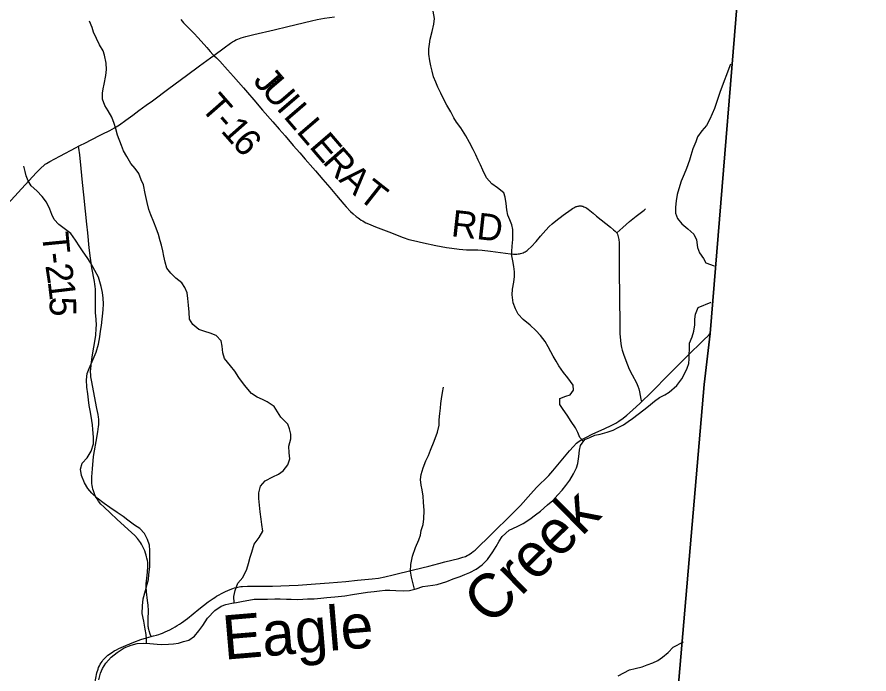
# Model space of a CAD drawing. Extents: x 1451455 to 1749751, y 218250 to 574981.
# Drawn here: x 1624093 to 1633736, y 328950 to 336380 of the extents above; entities that cross this region are included whole.
import ezdxf

# ---------------------------------------------------------------- set-up
doc = ezdxf.new("R2010")
doc.units = 0
for name, color, linetype in [('GM_X_Adjacent_County', 7, 'Continuous'), ('GM_X_County', 7, 'Continuous'), ('GM_X_County_Road', 7, 'Continuous'), ('GM_X_Minor_River', 7, 'Continuous'), ('GM_X_Minor_River_Text', 7, 'Continuous'), ('GM_X_Township', 7, 'Continuous'), ('GM_X_Township_Road', 7, 'Continuous'), ('GM_X_Township_Road_Text', 7, 'Continuous')]:
    doc.layers.add(name, color=color, linetype=linetype)

msp = doc.modelspace()

# ---------------------------------------------------------------- linework, layer by layer
at = {"layer": 'GM_X_Adjacent_County'}
msp.add_lwpolyline([(1628937.4, 298347.9), (1629433.5, 303775.2), (1629535.6, 304886.8), (1630089.4, 311112.5), (1630271.2, 313052.8), (1630419.2, 314553.1), (1630488.1, 315536.2), (1630722.1, 318179), (1630769.3, 318616.5), (1630954.3, 320912.7), (1631259.9, 324445.5), (1631493.2, 327825.1), (1631870, 332223.9), (1631938.7, 332800.9), (1632333.3, 337651.7), (1632719.3, 342502.4), (1633084.6, 347092.3), (1633092.9, 347196.5), (1633154.2, 348075.8), (1633223.5, 348841.9), (1633265.4, 349677.7), (1633735.7, 355307.8)], dxfattribs=at)
at = {"layer": 'GM_X_County'}
msp.add_lwpolyline([(1628937.4, 298347.9), (1629433.5, 303775.2), (1629535.6, 304886.8), (1630089.4, 311112.5), (1630271.2, 313052.8), (1630419.2, 314553.1), (1630488.1, 315536.2), (1630722.1, 318179), (1630769.3, 318616.5), (1630954.3, 320912.7), (1631259.9, 324445.5), (1631493.2, 327825.1), (1631870, 332223.9), (1631938.7, 332800.9), (1632333.3, 337651.7), (1632719.3, 342502.4), (1633084.6, 347092.3), (1633092.9, 347196.5), (1633154.2, 348075.8), (1633223.5, 348841.9), (1633265.4, 349677.7), (1633735.7, 355307.8)], dxfattribs=at)
at = {"layer": 'GM_X_County_Road'}
for points in [[(1631159.4, 332026.7), (1631263.8, 332125.8), (1631317.3, 332178.8), (1631434, 332298.6), (1631600.2, 332466.4), (1631643.9, 332510.9), (1631730.7, 332596), (1631811.6, 332672.8), (1631867.8, 332727.6), (1631918.3, 332779.8), (1631938.7, 332800.9)], [(1625610.6, 329374.1), (1625637.9, 329381.5), (1625671.2, 329390.2), (1625697.8, 329397.9), (1625717.1, 329404.2), (1625740.8, 329412.9), (1625770.6, 329425.3), (1625794.6, 329436.2), (1625824.4, 329450.5), (1625855.9, 329467), (1625881.9, 329481.2), (1625906.8, 329496.5), (1625932.6, 329513.1), (1625955.6, 329529.1), (1626021.1, 329578.1), (1626152.7, 329681.3), (1626258.3, 329764.8), (1626311.7, 329803.4), (1626330.8, 329815.8), (1626350.9, 329827.9), (1626380.9, 329844.6), (1626409.2, 329859.3), (1626446.2, 329877.3), (1626487.8, 329896.2), (1626535.1, 329916.1), (1626556.3, 329923.2), (1626573.1, 329927.9), (1626592.3, 329932.6), (1626608.9, 329935.4), (1626626.3, 329937.8), (1626645.1, 329939.7), (1626701.2, 329941.7), (1626986.5, 329944.3), (1627173.4, 329949.7), (1627274.7, 329955.5), (1627471, 329969.9), (1627628, 329982.3), (1627814.3, 329997.3), (1627945, 330009.3), (1628114.7, 330025.1), (1628186, 330034.9), (1628256.7, 330048), (1628349.1, 330069.6), (1628581.4, 330128.5), (1628753.4, 330170.4), (1628867.5, 330200), (1628934, 330217.9), (1629093.3, 330257), (1629139.4, 330269.6), (1629168.4, 330279.8), (1629189, 330288.6), (1629204.9, 330297), (1629221.8, 330307), (1629237.7, 330318), (1629257.1, 330333.6), (1629278.9, 330351.2), (1629326.9, 330397.5), (1629417.8, 330487.4), (1629527, 330596.4), (1629628.2, 330694.6), (1629733.8, 330797.6), (1629790.4, 330856.7), (1629908.4, 330988.8), (1629973.8, 331058.2), (1630111.2, 331194.4), (1630157.8, 331246.9), (1630345.5, 331472.7), (1630391.7, 331524.2), (1630427.1, 331558.9), (1630455.6, 331581.8), (1630486.2, 331601.7), (1630529.9, 331625.1), (1630609.6, 331664), (1630738.1, 331722.1), (1630824.1, 331762.4), (1630870, 331787.2), (1630905.9, 331809.7), (1630953.6, 331843.9), (1630994.1, 331876.8), (1631060.3, 331935.4), (1631144.9, 332012.9), (1631159.4, 332026.7)], [(1624973.5, 328843.6), (1624998.3, 328962.6), (1625010.2, 329004), (1625017.2, 329023.5), (1625025.3, 329040.9), (1625035.6, 329060.2), (1625044.8, 329075.8), (1625055.9, 329092.2), (1625066.2, 329105.5), (1625079.5, 329120.9), (1625092.9, 329135.1), (1625107, 329148), (1625122.7, 329161.5), (1625139.3, 329174.4), (1625154.8, 329185.1), (1625174, 329197.5), (1625194.2, 329209.5), (1625217.9, 329222.2), (1625246.7, 329237.3), (1625324.4, 329273), (1625415.5, 329310.8), (1625495.9, 329340.1), (1625558.6, 329360.1), (1625610.6, 329374.1)]]:
    msp.add_lwpolyline(points, dxfattribs=at)
at = {"layer": 'GM_X_Minor_River'}
for points in [[(1630504.1, 331580.4), (1630463.3, 331625.8), (1630442.1, 331680.1), (1630412.8, 331732.5), (1630365.9, 331807.2), (1630319, 331877.9), (1630273.9, 331942.5), (1630236.8, 331997.1), (1630235.7, 332065.2), (1630304.1, 332090.3), (1630354.3, 332107.6), (1630391, 332159.2), (1630387.8, 332215.3), (1630327.1, 332298.2), (1630278, 332358.9), (1630225.1, 332433.6), (1630195.9, 332486.1), (1630162.7, 332544.6), (1630133.5, 332595), (1630106.3, 332651.4), (1630069.2, 332710), (1630016.2, 332778.7), (1629965, 332833.4), (1629902, 332896.3), (1629820.9, 332957.4), (1629763.8, 333020.2), (1629734.7, 333080.7), (1629709.7, 333147.1), (1629697, 333239.3), (1629701.9, 333301.3), (1629715.1, 333381.2), (1629722, 333445.2), (1629722.8, 333499.2), (1629715.7, 333559.4), (1629704.6, 333623.6), (1629695.4, 333677.7), (1629694.1, 333729.8), (1629697, 333787.8), (1629704.1, 333865.8), (1629704.9, 333917.8), (1629703.7, 333975.9), (1629694.5, 334028.1), (1629669.3, 334086.5), (1629650.1, 334138.8), (1629637, 334199), (1629630, 334271.1), (1629619, 334341.3), (1629603.8, 334391.6), (1629530.6, 334448.6), (1629467.4, 334495.5), (1629408.3, 334560.3), (1629365.6, 334646.9), (1629338.5, 334709.3), (1629311.3, 334761.7), (1629286.2, 334822.1), (1629257.1, 334882.6), (1629214.2, 334961.2), (1629171.4, 335035.8), (1629116.7, 335126.6), (1629065.6, 335189.3), (1629036.4, 335239.8), (1629001.4, 335308.3), (1628958.5, 335384.9), (1628919.6, 335455.5), (1628888.5, 335519.9), (1628857.5, 335588.4), (1628832.3, 335642.8), (1628807.2, 335703.1), (1628790.2, 335767.4), (1628775, 335827.7), (1628765.9, 335885.8), (1628755, 335960), (1628753.9, 336020.1), (1628760.6, 336074.1), (1628769.4, 336130), (1628792.7, 336217.8), (1628809.9, 336299.6), (1628818.8, 336365.6), (1628802, 336447.8)], [(1626551.1, 329753.9), (1626545.3, 329827.1), (1626562.3, 329893), (1626591.5, 329976.7), (1626650.4, 330042), (1626693.7, 330133.5), (1626712.6, 330199.3), (1626731.7, 330271.1), (1626750.5, 330328.9), (1626775.8, 330418.7), (1626834.8, 330492), (1626875.8, 330563.5), (1626864.9, 330639.8), (1626857.8, 330699.9), (1626845, 330784.2), (1626836.1, 330860.3), (1626831.2, 330932.5), (1626830.1, 330998.6), (1626849.2, 331072.4), (1626902.1, 331133.8), (1626988.7, 331180.7), (1627051.1, 331209.9), (1627105.6, 331249.2), (1627156.6, 331316.6), (1627179.5, 331382.4), (1627172.5, 331452.5), (1627169.6, 331526.7), (1627192.8, 331608.4), (1627193.5, 331662.5), (1627178.4, 331720.7), (1627159.2, 331775), (1627080.4, 331854.1), (1627041.3, 331914.7), (1627004.1, 331973.2), (1626925, 332028.3), (1626871.4, 332053.1), (1626811.8, 332081.9), (1626746.5, 332122.8), (1626667.8, 332215.9), (1626605.2, 332304.8), (1626558.2, 332373.5), (1626509.1, 332436.1), (1626442.4, 332519.1), (1626423.3, 332583.4), (1626416.4, 332657.6), (1626403.3, 332717.8), (1626346.2, 332778.6), (1626278.6, 332805.5), (1626218.9, 332824.3), (1626151.3, 332847.2), (1626082.1, 332904.2), (1626047, 332964.7), (1626040.1, 333040.8), (1626035.3, 333121), (1626026.4, 333195.2), (1626017.3, 333259.3), (1625992.2, 333321.7), (1625959, 333372.2), (1625891.8, 333425.1), (1625834.7, 333483.9), (1625789.5, 333538.6), (1625768.5, 333608.9), (1625755.5, 333675.1), (1625744.4, 333735.3), (1625729.3, 333799.6), (1625714, 333849.8), (1625695.1, 333920.2), (1625668.1, 333992.6), (1625641.1, 334061), (1625606.3, 334143.5), (1625585.2, 334203.9), (1625564.4, 334282.2), (1625543.9, 334384.6), (1625523.3, 334480.9), (1625500.1, 334539.3), (1625471.2, 334609.7), (1625430, 334668.3), (1625380.9, 334723), (1625336, 334801.7), (1625297, 334866.2), (1625275.9, 334928.6), (1625229.6, 335043.3), (1625212.7, 335117.6), (1625193.6, 335177.9), (1625166.6, 335246.3), (1625125.6, 335318.9), (1625086.6, 335381.4), (1625059.6, 335451.8), (1625060.6, 335517.9), (1625067.3, 335569.8), (1625078.1, 335621.8), (1625099.4, 335717.6), (1625104.4, 335785.6), (1625101.5, 335857.7), (1625084.8, 335948), (1625067.5, 335998.2), (1625028.5, 336064.8), (1624993.6, 336137.3), (1624960.6, 336207.8), (1624943.4, 336260.1), (1624912.4, 336332.5)], [(1632166.7, 335848.2), (1632051, 335536.7), (1632028.1, 335471), (1632011.3, 335413.1), (1631986.3, 335345.4), (1631961.5, 335285.7), (1631934.6, 335226), (1631897.6, 335154.4), (1631844.7, 335093), (1631793.7, 335023.6), (1631774.9, 334967.8), (1631743.8, 334888.1), (1631720.8, 334814.4), (1631704, 334762.5), (1631668.7, 334668.9), (1631645.7, 334603.2), (1631610.6, 334523.5), (1631583.4, 334437.8), (1631566.4, 334372), (1631553.4, 334300.1), (1631546.4, 334230.1), (1631547.4, 334162), (1631570.5, 334101.7), (1631617.6, 334043), (1631686.8, 333986.1), (1631751.8, 333923.1), (1631784.9, 333860.7), (1631793.6, 333774.5), (1631816.7, 333712.1), (1631861.8, 333649.5), (1631891.1, 333599), (1631981.9, 333566.7)], [(1625558.8, 329295.6), (1625556.9, 329345.5), (1625553.6, 329397.6), (1625544.5, 329455.8), (1625529.8, 329546), (1625511.1, 329632.4), (1625512.3, 329720.5), (1625521.5, 329798.4), (1625546.8, 329894.2), (1625567.8, 329964), (1625580.6, 330017.8), (1625585.4, 330073.8), (1625596.7, 330161.8), (1625598.1, 330261.9), (1625597.4, 330348), (1625592.3, 330408.1), (1625571.2, 330472.4), (1625534.2, 330539), (1625483, 330593.7), (1625421.6, 330634.5), (1625346.4, 330687.6), (1625293.1, 330732.3), (1625227.8, 330777.2), (1625142.6, 330832.4), (1625079.4, 330879.2), (1625000.3, 330938.3), (1624941.1, 330995.1), (1624893.9, 331045.8), (1624856.8, 331112.4), (1624824, 331192.9), (1624811.1, 331267.1), (1624832, 331332.9), (1624888.9, 331396.2), (1624932, 331469.7), (1624959.1, 331551.5), (1624958.3, 331629.6), (1624951.5, 331713.7), (1624948.3, 331765.8), (1624941, 331816), (1624924.4, 331910.3), (1624909.4, 331984.5), (1624902.4, 332048.7), (1624893.4, 332118.9), (1624882.5, 332193.1), (1624879.7, 332275.2), (1624888.7, 332347.2), (1624909.5, 332405), (1624944.7, 332484.6), (1624988.2, 332590.1), (1625013.5, 332679.9), (1625030.7, 332763.7), (1625039.6, 332825.7), (1625050.5, 332891.6), (1625069, 333067.5), (1625070.1, 333137.6), (1625067, 333201.7), (1625059.9, 333265.8), (1625044.9, 333332.1), (1625029.7, 333386.3), (1625014.4, 333436.6), (1624975.6, 333513.2), (1624928.8, 333595.8), (1624887.7, 333660.4), (1624842.7, 333723.1), (1624805.5, 333781.6), (1624754.6, 333856.4), (1624701.8, 333931.1), (1624628.6, 333990.1), (1624565.3, 334033), (1624514.2, 334091.7), (1624487, 334146.1), (1624463.9, 334208.5), (1624427, 334285), (1624376, 334351.8), (1624316.9, 334412.6), (1624251.8, 334471.5), (1624218.6, 334526), (1624195.5, 334582.3), (1624184.2, 334632.5), (1624169.1, 334692.8)], [(1630771.9, 331685.8), (1630842.2, 331706.9), (1630898.6, 331736.2), (1630959, 331767.4), (1631009.5, 331804.8), (1631060, 331838.2), (1631124.7, 331889.4), (1631189.4, 331938.6), (1631239.9, 331978), (1631306.8, 332037.1), (1631363.3, 332076.5), (1631425.7, 332107.7), (1631476.1, 332139), (1631561.1, 332212), (1631616.2, 332287.4), (1631649, 332343), (1631679.9, 332408.6), (1631696.7, 332462.5), (1631701.5, 332514.5), (1631702.2, 332568.5), (1631702.9, 332618.5), (1631706, 332690.6), (1631733, 332764.3), (1631754, 332828.1), (1631765, 332900), (1631765.9, 332962.1), (1631772.7, 333020), (1631801.8, 333093.7), (1631948.5, 333153.7)], [(1628592.9, 329909.6), (1628574.5, 329984.8), (1628559.4, 330045.1), (1628548.4, 330111.3), (1628551.5, 330189.3), (1628570.8, 330283.1), (1628602.2, 330380.8), (1628639.4, 330466.4), (1628660.2, 330520.2), (1628669, 330572.1), (1628690, 330642), (1628696.9, 330703.9), (1628702.2, 330797.9), (1628695.6, 330892.1), (1628688.6, 330960.3), (1628677.6, 331032.5), (1628668.4, 331084.7), (1628659.3, 331148.8), (1628668.1, 331204.8), (1628689.2, 331280.6), (1628720.3, 331360.3), (1628749.2, 331421.9), (1628774, 331479.7), (1628815.5, 331583.2), (1628853, 331684.8), (1628872.1, 331764.7), (1628873, 331824.7), (1628880, 331894.7), (1628884.9, 331954.7), (1628891.6, 332008.6), (1628896.4, 332060.6), (1628907.4, 332132.6), (1628920.3, 332194.5)], [(1625018.5, 328884), (1625039.6, 328957.8), (1625060.3, 329009.6), (1625099.2, 329071.2), (1625160.1, 329140.4), (1625226.9, 329193.6), (1625305.6, 329244.6), (1625384, 329275.7), (1625452.2, 329292.8), (1625528.2, 329297.8), (1625598.1, 329292.9), (1625678, 329285.8), (1625729.9, 329281.2), (1625807.9, 329286.2), (1625865.9, 329291.4), (1625922, 329298.7), (1625978.2, 329316), (1626036.5, 329333.2), (1626101.1, 329378.4), (1626151.9, 329437.8), (1626194.8, 329499.3), (1626249.9, 329580.7), (1626333.1, 329667.7), (1626403.8, 329716.8), (1626456, 329734.2), (1626524.2, 329749.3), (1626578.3, 329758.6), (1626654.5, 329773.6), (1626716.6, 329784.8), (1626778.7, 329794), (1626864.7, 329794.9), (1626926.7, 329796.1), (1627010.7, 329799), (1627070.6, 329798.2), (1627142.5, 329795.3), (1627194.5, 329794.6), (1627270.4, 329793.6), (1627328.4, 329794.9), (1627380.5, 329798.2), (1627456.5, 329801.2), (1627532.5, 329808.2), (1627598.6, 329815.4), (1627690.6, 329822.2), (1627802.8, 329834.7), (1627890.9, 329847.6), (1628059.2, 329873.4), (1628135.3, 329882.4), (1628197.4, 329891.6), (1628261.4, 329898.8), (1628313.4, 329898.1), (1628379.3, 329893.3), (1628463.2, 329888.2), (1628535.2, 329893.2), (1628609.5, 329914.3), (1628687.8, 329937.3), (1628797.9, 329953.9), (1628850, 329963.2), (1628956.5, 329995.8), (1629030.8, 330024.9), (1629107.2, 330051.9), (1629161.5, 330075.2), (1629217.8, 330096.5), (1629288.3, 330135.6), (1629359, 330184.8), (1629419.8, 330246), (1629477, 330329.4), (1629515.9, 330392.9), (1629550.8, 330452.5), (1629585.5, 330504.1), (1629662.5, 330577.2), (1629753, 330616), (1629821.5, 330651.2), (1629896.2, 330700.2), (1629962.8, 330749.4), (1630019.4, 330792.7), (1630098.4, 330861.8), (1630159.1, 330913), (1630214, 330974.4), (1630262.7, 331027.8), (1630303.5, 331083.3), (1630348.3, 331142.8), (1630391.3, 331212.3), (1630426.3, 331279.9), (1630439, 331331.8), (1630450.1, 331409.7), (1630461.2, 331481.6), (1630471.9, 331535.6), (1630518.9, 331601), (1630577.2, 331624.3), (1630633.5, 331649.6), (1630693.7, 331662.8), (1630771.9, 331685.8)], [(1630896, 328929.4), (1630960.4, 328962.6), (1631024.9, 328995.8), (1631091.1, 329013), (1631167.3, 329032), (1631225.6, 329051.2), (1631287.9, 329074.5), (1631344.2, 329101.8), (1631398.7, 329139.1), (1631461.5, 329194.3), (1631518.3, 329251.6), (1631637.4, 329311.6)]]:
    msp.add_lwpolyline(points, dxfattribs=at)
at = {"layer": 'GM_X_Township'}
msp.add_lwpolyline([(1612953.2, 349181.6), (1616266, 348982.3), (1620694.6, 348714.5), (1624118.7, 348496.2), (1625557.2, 348428.9), (1631303.5, 348160.1), (1631517, 348150.1), (1633154.2, 348075.8), (1633092.9, 347196.5), (1633084.6, 347092.3), (1632719.3, 342502.4), (1632333.3, 337651.7), (1631938.7, 332800.9), (1631870, 332223.9), (1631493.2, 327825.1), (1631259.9, 324445.5)], dxfattribs=at)
at = {"layer": 'GM_X_Township_Road'}
for points in [[(1625945.5, 336350.9), (1625977.6, 336315.2), (1626004.6, 336286.6), (1626037.8, 336254.9), (1626080.2, 336214.1), (1626096.2, 336197.6), (1626143, 336146.9), (1626240.4, 336035.7), (1626279.5, 335991.3), (1626310, 335958.4), (1626320.7, 335946.9)], [(1626320.7, 335946.9), (1626439.3, 336033.4), (1626511.2, 336085.1), (1626533.1, 336099.2), (1626553, 336111), (1626571.6, 336120.7), (1626591.1, 336129.9), (1626611.2, 336138.2), (1626630.9, 336145.2), (1626654.9, 336153.1), (1626681.2, 336160.1), (1626773.6, 336183), (1627003.7, 336236.2), (1627156.8, 336273.1), (1627424.7, 336338), (1627488.8, 336351.6), (1627572.9, 336365.9), (1627686.3, 336383.7)], [(1624915.7, 334983), (1625057.6, 335053.9), (1625145.1, 335098.7), (1625196.6, 335127.6), (1625252.1, 335162.6), (1625324.8, 335213.2), (1625403.8, 335271.8), (1625471.8, 335323), (1625553.7, 335382.8), (1625625.9, 335434), (1625813.2, 335572.5), (1626011, 335718.7), (1626159.1, 335827.3), (1626282.9, 335919.3), (1626320.7, 335946.9)], [(1626320.7, 335946.9), (1626350.1, 335920.1), (1626387.9, 335881.7), (1626475.2, 335783.8), (1626542.8, 335707.9), (1626599.7, 335644.3), (1626657.8, 335577.7), (1626702.2, 335525.1), (1626771.6, 335444.8), (1626873.4, 335326.5), (1626987.5, 335195.4), (1627060.7, 335111.2), (1627127.9, 335035), (1627220.3, 334928.4), (1627293.6, 334844.4), (1627356.1, 334772.7), (1627442.1, 334673.8), (1627470.1, 334641.6), (1627513.2, 334592.3), (1627556.2, 334542.8), (1627634.8, 334450.4), (1627710.7, 334359.9), (1627793.5, 334262.4), (1627819.6, 334233), (1627869.2, 334180.7), (1627897.6, 334153.4), (1627932.4, 334123.5), (1627952.6, 334108.6), (1627969.3, 334096.5), (1627987.7, 334084.1), (1628005.3, 334073.7), (1628022.2, 334063.9), (1628043, 334054), (1628069.9, 334041.9), (1628152.1, 334008.8), (1628301.4, 333949.2), (1628463.8, 333887.2), (1628529, 333864.9), (1628579.5, 333850.9), (1628694.8, 333825.4), (1628833.1, 333797.5), (1628952.3, 333774.6), (1629013.9, 333765), (1629098.6, 333755.1), (1629180.3, 333748.8), (1629268.5, 333746.9), (1629307.6, 333746.2), (1629359.6, 333743.3), (1629453.7, 333733.7), (1629677.5, 333703), (1629713.4, 333699.7), (1629729.5, 333699.1), (1629749.5, 333699.6), (1629765.3, 333700.9), (1629778.9, 333702.9), (1629792.6, 333705.9), (1629807.5, 333709.5), (1629820.6, 333714), (1629831.8, 333718.9), (1629844.7, 333725.7), (1629854.4, 333731.7), (1629867.3, 333740.6), (1629877.8, 333749.4), (1629910.8, 333780.9), (1629968.3, 333843.2), (1630019.6, 333902.1), (1630077.5, 333968.7), (1630115.4, 334009.5), (1630148.9, 334040.9), (1630191.8, 334076.5), (1630273, 334137.7), (1630363.5, 334202.8), (1630380.7, 334214.1), (1630396.9, 334223.7), (1630407.9, 334230.1), (1630419.9, 334235.5), (1630429.6, 334238.7), (1630439.2, 334241.4), (1630446.7, 334242.9), (1630455.2, 334244.1), (1630462.4, 334244.4), (1630471.6, 334244.3), (1630479.4, 334243.4), (1630487.7, 334242), (1630498, 334239.4), (1630509.5, 334235.1), (1630521.7, 334229.5), (1630530.1, 334224.8), (1630542.3, 334216.8), (1630557.3, 334206.4), (1630613.3, 334160.8), (1630653.7, 334127.4), (1630809.8, 334002.2), (1630844.8, 333972.5), (1630862.8, 333956.9), (1630880.2, 333939.5)], [(1624789.1, 334918.1), (1624881.7, 334965.9), (1624915.7, 334983)], [(1623989.4, 334267.6), (1624145, 334436.4), (1624231.5, 334530.7), (1624311.5, 334617.6), (1624364.3, 334671.4), (1624400.9, 334704.3), (1624413.5, 334714.6), (1624427.1, 334724), (1624466.2, 334748), (1624576.5, 334806.1), (1624762.2, 334904.2), (1624789.1, 334918.1)], [(1625610.6, 329374.1), (1625601.2, 329401.1), (1625588.3, 329438.1), (1625584.5, 329452.7), (1625581.8, 329463.5), (1625579.6, 329475.3), (1625578.6, 329486.2), (1625577.3, 329515.6), (1625578.9, 329564.7), (1625580, 329669.3), (1625577, 329728.5), (1625571, 329781.3), (1625558.9, 329879), (1625557.4, 329899.4), (1625556.3, 329917), (1625556.2, 329969.2), (1625561.2, 330034.5), (1625569.5, 330102), (1625574, 330163.9), (1625574.3, 330188.8), (1625572.8, 330211.1), (1625569.5, 330234.8), (1625564.2, 330258.6), (1625559.6, 330275.2), (1625553.5, 330294.9), (1625546.8, 330317.1), (1625538.2, 330341.6), (1625528.7, 330364.6), (1625521.8, 330381), (1625511, 330402.7), (1625502.2, 330418.8), (1625492.1, 330435.2), (1625481, 330451.9), (1625469.8, 330466.9), (1625456.7, 330482.9), (1625427.5, 330514), (1625353, 330583.3), (1625223.1, 330700.8), (1625151, 330767.2), (1625074, 330840.7), (1625042.7, 330872.1), (1625017.1, 330904.1), (1624999, 330930.9), (1624982.7, 330957.3), (1624970.7, 330986.4), (1624957.5, 331021.5), (1624952.2, 331040), (1624947.3, 331061.4), (1624943.9, 331080.7), (1624941.2, 331102.9), (1624940.1, 331138.4), (1624941.5, 331180.1), (1624945.8, 331269), (1624959.7, 331408.2), (1624969.6, 331473.9), (1624988.6, 331580.5), (1625008.3, 331687), (1625016.8, 331748.7), (1625018.6, 331768.5), (1625018.9, 331788.1), (1625018.6, 331807.4), (1625017.3, 331830.6), (1625015.2, 331854.2), (1625011.4, 331883.9), (1624997.9, 331953.7), (1624957.9, 332153.2), (1624939.3, 332253.2), (1624929.2, 332311.8), (1624926.9, 332337.1), (1624926.1, 332362), (1624926.5, 332379), (1624927.3, 332398.6), (1624932.6, 332444.6), (1624945, 332535.2), (1624980.9, 332754), (1624983.9, 332781.6), (1624989.9, 332856.2), (1624991, 332899.6), (1624987.3, 332956.2), (1624983.9, 333003.4), (1624981.6, 333032.4), (1624980.1, 333074.3), (1624981.3, 333150.7), (1624982.9, 333206.3), (1624982.1, 333271.9), (1624980.9, 333301.8), (1624977.9, 333330.8), (1624975.2, 333356.9), (1624970, 333389.3), (1624941.2, 333544.1), (1624923.5, 333654.3), (1624909.6, 333768.2), (1624893.3, 333941.2), (1624885, 334036), (1624869.8, 334186.2), (1624850.1, 334368.8), (1624834.5, 334509), (1624817.9, 334668.9), (1624803.7, 334822.5), (1624792.4, 334896.9), (1624789.1, 334918.1)], [(1630880.2, 333939.5), (1630951.8, 334001.4), (1631025.8, 334066.6), (1631099, 334127.6), (1631190.1, 334197.5), (1631204.7, 334210.2)], [(1630880.2, 333939.5), (1630884.3, 333933.2), (1630889.1, 333923.5), (1630893.8, 333910), (1630898.6, 333894.1), (1630903.7, 333865), (1630906.8, 333825.8), (1630907.9, 333763.5), (1630908.1, 333691.3), (1630909.8, 333481.2), (1630912.2, 333241.7), (1630913.5, 333084.3), (1630914.9, 333028.6), (1630915.2, 332959.7), (1630915.6, 332921.2), (1630916.2, 332868), (1630917.1, 332799.2), (1630918.8, 332760), (1630921.7, 332724.2), (1630927.4, 332682), (1630935.6, 332643.6), (1630943.8, 332612), (1630957.1, 332568.1), (1630971.6, 332524.9), (1631001.4, 332445.5), (1631022.5, 332397.6), (1631054.7, 332333.3), (1631102.8, 332244.1), (1631120.7, 332205.6), (1631131.6, 332175), (1631140.2, 332140.3), (1631147.1, 332098.4), (1631154.2, 332057), (1631159.4, 332026.7)]]:
    msp.add_lwpolyline(points, dxfattribs=at)

# ---------------------------------------------------------------- texts
at = {"layer": 'GM_X_Minor_River_Text'}
for s, height, rotation, p in [('Creek', 500.01, 44.53264, (1629452.1, 329482.7)), ('Eagle', 499.99, 4.8417, (1626439.5, 329109.9))]:
    msp.add_text(s, height=height, rotation=rotation, dxfattribs=at).set_placement(p)
at = {"layer": 'GM_X_Township_Road_Text'}
for s, rotation, p in [('J', 310.6539, (1626756, 335652.9)), ('U', 310.65663, (1626847.7, 335546.1)), ('T', 311.22746, (1626160.5, 335351.3)), ('I', 310.6521, (1627019.7, 335345.8)), ('L', 310.65709, (1627100, 335252.3)), ('-', 311.25201, (1626308.5, 335182.5)), ('1', 311.39217, (1626390.3, 335089.2)), ('L', 310.65336, (1627246.2, 335082.1)), ('6', 312.06212, (1626515, 334947.8)), ('E', 310.65424, (1627392.4, 334911.8)), ('R', 311.34623, (1627541.2, 334738.6)), ('A', 316.93275, (1627726.2, 334530.7)), ('T', 321.7675, (1627940.1, 334332.4)), ('RD', 353.65629, (1628998.8, 333902.2)), ('T', 275.55005, (1624374.6, 333934.2)), ('-', 276.42627, (1624396.8, 333705.8)), ('2', 278.80119, (1624412.4, 333570)), ('1', 276.88071, (1624440.3, 333390)), ('5', 270.66091, (1624461.9, 333215.1))]:
    msp.add_text(s, height=300, rotation=rotation, dxfattribs=at).set_placement(p)

doc.saveas('drawing.dxf')
